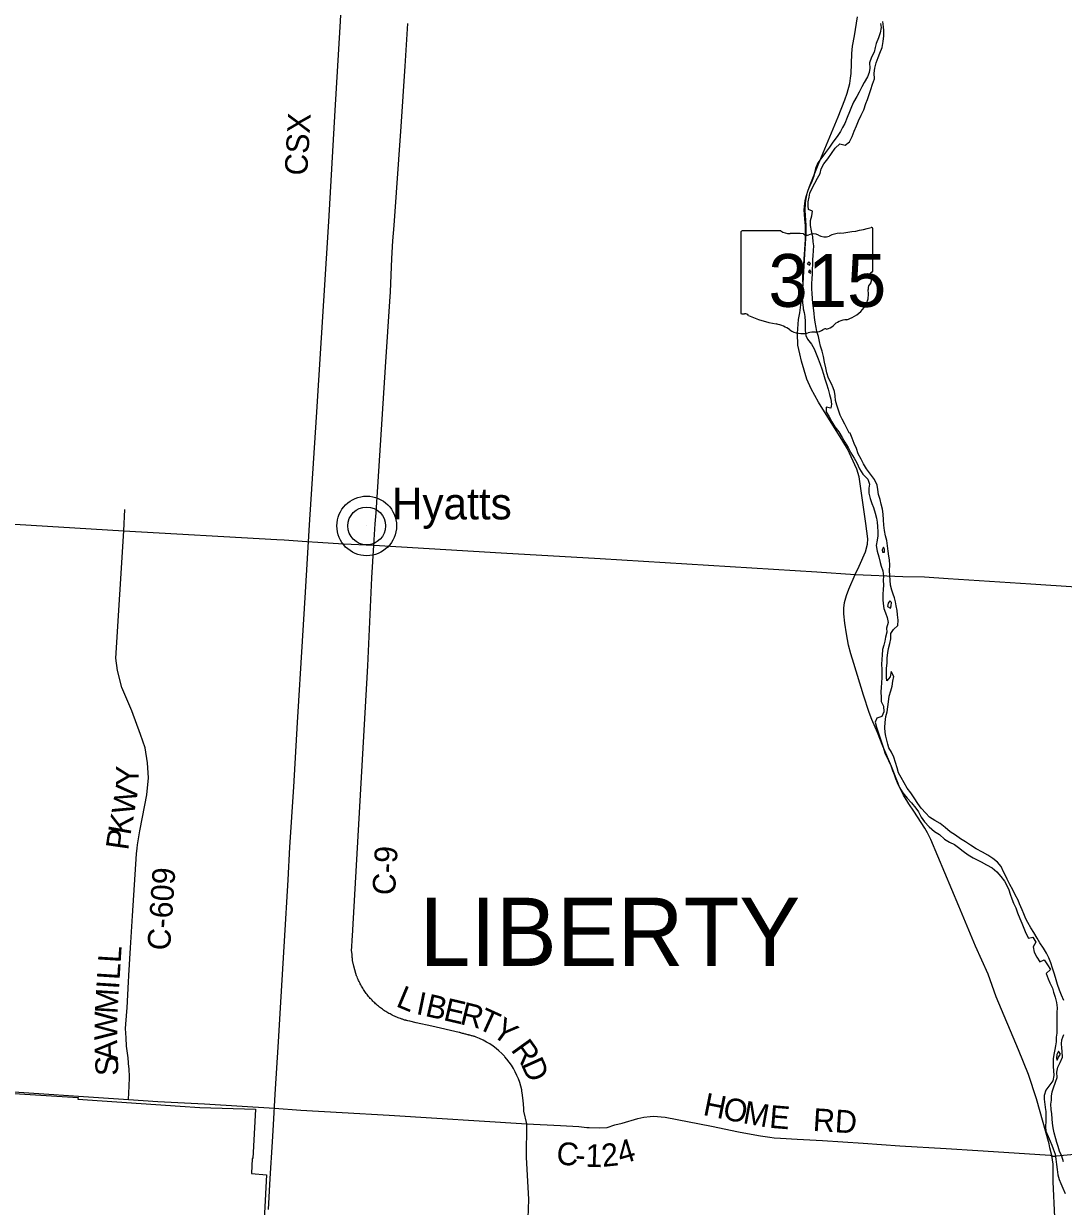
# Model space of a CAD drawing. Extents: x 1674899 to 2057726, y 653888 to 988278.
# Drawn here: x 1800519 to 1814222, y 798950 to 814535 of the extents above; entities that cross this region are included whole.
import ezdxf

# ---------------------------------------------------------------- set-up
doc = ezdxf.new("R2010")
doc.units = 0
for name, color, linetype in [('GM_X_Corporation', 7, 'Continuous'), ('GM_X_County_Road', 7, 'Continuous'), ('GM_X_County_Road_Text', 7, 'Continuous'), ('GM_X_Major_River', 7, 'Continuous'), ('GM_X_Rail_Line', 7, 'Continuous'), ('GM_X_Rail_Line_Text', 7, 'Continuous'), ('GM_X_State_Location', 7, 'Continuous'), ('GM_X_State_Route', 7, 'Continuous'), ('GM_X_State_Shield', 7, 'Continuous'), ('GM_X_Township_Text', 7, 'Continuous'), ('GM_X_Unincorporated', 7, 'Continuous'), ('GM_X_Unincorporated_Location', 7, 'Continuous'), ('GM_X_Unincorporated_Text', 7, 'Continuous')]:
    doc.layers.add(name, color=color, linetype=linetype)

msp = doc.modelspace()

# ---------------------------------------------------------------- linework, layer by layer
at = {"layer": 'GM_X_Corporation'}
msp.add_lwpolyline([(1800039, 800457), (1801236, 800382), (1801235, 800362), (1802581, 800268), (1802843, 800252), (1803573, 800232), (1803539, 799580), (1803531, 799580), (1803521, 799381), (1803720, 799367), (1803650, 798018)], dxfattribs=at)
at = {"layer": 'GM_X_County_Road'}
for points in [[(1804844, 802293), (1804843, 802302), (1804842, 802313), (1804841, 802319), (1804844, 802370), (1804849, 802458), (1804852, 802514), (1805055, 806072), (1805110, 807232), (1805136, 807661), (1805154, 807942), (1805164, 808090), (1805292, 810078), (1805346, 810873), (1805352, 810999), (1805373, 811438), (1805385, 811671), (1805404, 811873), (1805495, 813180), (1805546, 813974), (1805583, 814537)], [(1797153, 808138), (1797813, 808094), (1798478, 808064), (1798746, 808039), (1801838, 807850), (1803855, 807737), (1803954, 807731), (1804251, 807713), (1804397, 807702), (1804736, 807682), (1805136, 807661), (1806811, 807563), (1808119, 807486), (1809547, 807399), (1810973, 807310), (1811477, 807276), (1812106, 807251), (1812390, 807244), (1812704, 807223), (1813792, 807154), (1815652, 807028), (1817412, 806933), (1818544, 806864), (1818913, 806840)], [(1801838, 807850), (1801854, 808132)], [(1802014, 803669), (1802020, 803715), (1802050, 803896), (1802085, 804077), (1802143, 804374), (1802164, 804595), (1802153, 804796), (1802119, 804993), (1802057, 805167), (1801945, 805481), (1801815, 805789), (1801757, 806010), (1801735, 806174), (1801838, 807850)], [(1801953, 802776), (1801962, 802915), (1802006, 803596), (1802014, 803669)], [(1801927, 802355), (1801953, 802776)], [(1801904, 801987), (1801904, 801993), (1801927, 802355)], [(1806860, 800922), (1806855, 800928), (1806820, 800964), (1806783, 800999), (1806745, 801031), (1806705, 801061), (1806663, 801090), (1806620, 801115), (1806575, 801139), (1806529, 801160), (1806483, 801179), (1806464, 801186), (1806456, 801189), (1806449, 801191), (1806443, 801192), (1806431, 801196), (1806423, 801198), (1806414, 801200), (1806401, 801204), (1806388, 801207), (1806381, 801209), (1806371, 801212), (1806359, 801215), (1806347, 801218), (1806336, 801220), (1806324, 801223), (1806314, 801226), (1806302, 801229), (1806289, 801233), (1806283, 801235), (1806276, 801237), (1806266, 801239), (1806257, 801241), (1805899, 801322), (1805693, 801369), (1805607, 801388), (1805581, 801394), (1805570, 801397), (1805562, 801399), (1805554, 801401), (1805547, 801403), (1805539, 801405), (1805530, 801408), (1805521, 801412), (1805511, 801415), (1805503, 801418), (1805495, 801421), (1805486, 801424), (1805470, 801430), (1805454, 801436), (1805439, 801442), (1805424, 801449), (1805408, 801455), (1805393, 801462), (1805386, 801466), (1805378, 801470), (1805363, 801477), (1805349, 801485), (1805334, 801493), (1805319, 801501), (1805305, 801510), (1805291, 801518), (1805277, 801527), (1805263, 801537), (1805249, 801546), (1805236, 801556), (1805223, 801566), (1805209, 801576), (1805196, 801586), (1805184, 801597), (1805171, 801608), (1805158, 801619), (1805146, 801630), (1805134, 801642), (1805122, 801654), (1805111, 801666), (1805099, 801678), (1805088, 801690), (1805077, 801703), (1805066, 801715), (1805056, 801728), (1805045, 801741), (1805035, 801755), (1805025, 801768), (1805016, 801782), (1805006, 801795), (1804997, 801809), (1804988, 801823), (1804980, 801838), (1804971, 801852), (1804963, 801867), (1804955, 801881), (1804948, 801896), (1804940, 801911), (1804933, 801926), (1804926, 801941), (1804920, 801957), (1804914, 801972), (1804911, 801979), (1804907, 801988), (1804896, 802019), (1804882, 802065), (1804869, 802115), (1804855, 802189), (1804854, 802197), (1804852, 802214), (1804850, 802230), (1804849, 802247), (1804848, 802263), (1804847, 802274), (1804844, 802293), (1804844, 802293)], [(1801882, 801567), (1801899, 801907), (1801904, 801987)], [(1801907, 800780), (1801897, 800907), (1801875, 801062), (1801868, 801169), (1801863, 801294), (1801880, 801518), (1801882, 801567)], [(1801901, 800359), (1801911, 800535), (1801912, 800648), (1801908, 800771), (1801907, 800780)], [(1807152, 800038), (1807113, 800206), (1807110, 800245), (1807102, 800345), (1807090, 800444), (1807086, 800469), (1807083, 800485), (1807071, 800534), (1807057, 800582), (1807040, 800629), (1807020, 800676), (1806999, 800721), (1806974, 800766), (1806948, 800808), (1806919, 800850), (1806888, 800890), (1806860, 800922)], [(1796520, 800687), (1796632, 800682), (1798065, 800600), (1798576, 800566), (1800057, 800481), (1801901, 800359), (1802286, 800331), (1802901, 800301), (1803824, 800245), (1804171, 800217), (1804715, 800188)], [(1804715, 800188), (1804715, 800188), (1805337, 800150)], [(1805337, 800150), (1807152, 800038)], [(1807071, 796914), (1807086, 797176), (1807115, 797807), (1807169, 798793), (1807176, 799039), (1807148, 799599), (1807152, 800038)], [(1807152, 800038), (1807595, 800015), (1807835, 800002), (1807942, 799990), (1807972, 799989)], [(1807972, 799989), (1808102, 799984), (1808211, 799987), (1808312, 800022), (1808409, 800047), (1808615, 800108), (1808695, 800123), (1808776, 800134), (1808826, 800138), (1808921, 800131), (1808973, 800123), (1809585, 800007), (1809940, 799932), (1810107, 799900), (1810229, 799878), (1810291, 799868), (1810353, 799860), (1810412, 799854), (1810492, 799848), (1810714, 799837), (1811046, 799817), (1811584, 799784), (1812065, 799747), (1812676, 799710), (1813093, 799684), (1813708, 799647), (1814050, 799626), (1814069, 799619)], [(1814069, 799619), (1814069, 799619), (1814083, 799612), (1814092, 799610), (1814102, 799610), (1814111, 799611), (1814133, 799614), (1814460, 799647), (1814566, 799659)]]:
    msp.add_lwpolyline(points, dxfattribs=at)
at = {"layer": 'GM_X_Major_River'}
for points in [[(1811812, 814536), (1811819, 814486), (1811809, 814412), (1811785, 814346), (1811754, 814274), (1811740, 814222), (1811730, 814158), (1811693, 814092), (1811667, 814020), (1811672, 813948), (1811664, 813892), (1811642, 813832), (1811597, 813760), (1811567, 813704), (1811530, 813634)], [(1811640, 813535), (1811685, 813667), (1811705, 813737), (1811731, 813809), (1811730, 813881), (1811738, 813949), (1811755, 814017), (1811783, 814091), (1811805, 814145), (1811832, 814219), (1811846, 814299), (1811855, 814375), (1811857, 814443), (1811853, 814495), (1811844, 814564)], [(1811530, 813634), (1811500, 813576), (1811458, 813502), (1811431, 813438), (1811403, 813375), (1811372, 813299), (1811344, 813219), (1811312, 813167), (1811287, 813113), (1811241, 813047), (1811185, 812971), (1811138, 812906), (1811088, 812836), (1811040, 812772), (1810985, 812702), (1810955, 812624), (1810944, 812574), (1810932, 812524), (1810906, 812456), (1810875, 812388), (1810853, 812336), (1810833, 812265), (1810814, 812199), (1810806, 812126), (1810803, 812076), (1810807, 812026), (1810811, 811960), (1810818, 811876), (1810820, 811816), (1810819, 811690), (1810817, 811624), (1810810, 811558), (1810806, 811497), (1810801, 811431), (1810799, 811367), (1810791, 811301), (1810786, 811225), (1810782, 811153), (1810787, 811101), (1810785, 811043), (1810781, 810973), (1810780, 810923), (1810782, 810855), (1810792, 810796)], [(1811397, 809144), (1811367, 809206), (1811340, 809259), (1811308, 809325), (1811280, 809377), (1811263, 809427), (1811235, 809506), (1811220, 809570), (1811214, 809630), (1811204, 809688), (1811187, 809738), (1811165, 809790), (1811128, 809865), (1811106, 809933), (1811092, 809999), (1811075, 810072), (1811063, 810150), (1811042, 810218), (1811022, 810286), (1811007, 810348), (1810995, 810413), (1810973, 810477), (1810962, 810531), (1810950, 810603), (1810943, 810663), (1810937, 810715), (1810929, 810788), (1810920, 810850), (1810916, 810910), (1810911, 810982), (1810909, 811034), (1810905, 811110), (1810912, 811174), (1810914, 811238), (1810917, 811304), (1810919, 811356), (1810921, 811425), (1810924, 811475), (1810930, 811545), (1810932, 811607), (1810923, 811659), (1810919, 811727), (1810904, 811803), (1810888, 811874), (1810889, 811942), (1810907, 812002), (1810915, 812066), (1810861, 812086), (1810858, 812136), (1810860, 812188), (1810872, 812250), (1810881, 812302), (1810913, 812368), (1810947, 812434), (1810980, 812498), (1811016, 812562), (1811031, 812620), (1811067, 812686), (1811119, 812755), (1811166, 812825), (1811216, 812895), (1811276, 812953), (1811348, 812932), (1811405, 812978), (1811437, 813046), (1811467, 813116), (1811494, 813190), (1811522, 813254), (1811557, 813329), (1811591, 813401), (1811619, 813483), (1811640, 813535)], [(1810869, 811395), (1810845, 811371), (1810875, 811353)], [(1810875, 811353), (1810891, 811375), (1810869, 811395)], [(1810879, 811289), (1810864, 811271), (1810888, 811247)], [(1810888, 811247), (1810892, 811261), (1810879, 811289)], [(1810792, 810796), (1810793, 810778), (1810807, 810728), (1810817, 810678), (1810820, 810610), (1810820, 810560), (1810818, 810492), (1810827, 810426), (1810851, 810375), (1810902, 810311), (1810940, 810251), (1810962, 810182), (1810989, 810116), (1811019, 810046), (1811038, 809986), (1811060, 809915), (1811078, 809853), (1811101, 809787), (1811121, 809719), (1811138, 809650), (1811156, 809586), (1811165, 809520), (1811159, 809466), (1811097, 809480), (1811097, 809420), (1811136, 809354), (1811172, 809288), (1811210, 809223), (1811261, 809157), (1811305, 809083), (1811344, 809018), (1811388, 808950), (1811423, 808880), (1811463, 808809), (1811498, 808749), (1811534, 808668), (1811581, 808600), (1811647, 808534), (1811665, 808465), (1811660, 808415), (1811660, 808347), (1811677, 808279), (1811699, 808213), (1811719, 808159), (1811740, 808084), (1811758, 808020), (1811767, 807966), (1811773, 807908), (1811777, 807838), (1811776, 807786), (1811768, 807730), (1811757, 807658), (1811767, 807584), (1811788, 807507), (1811806, 807435), (1811822, 807385), (1811841, 807325), (1811851, 807253), (1811847, 807200), (1811850, 807136), (1811846, 807080), (1811841, 807018), (1811845, 806942), (1811849, 806892), (1811858, 806826), (1811878, 806772), (1811901, 806708), (1811911, 806645), (1811893, 806571), (1811894, 806517), (1811880, 806449), (1811868, 806399), (1811855, 806345), (1811839, 806289), (1811832, 806215), (1811828, 806159), (1811826, 806091), (1811829, 806027), (1811829, 805921), (1811826, 805845), (1811820, 805793), (1811815, 805727), (1811821, 805661), (1811823, 805603), (1811850, 805540), (1811858, 805468), (1811831, 805406), (1811765, 805385), (1811741, 805329), (1811759, 805265), (1811780, 805197), (1811800, 805146), (1811847, 805002), (1811868, 804928), (1811892, 804878), (1811918, 804823), (1811947, 804759), (1811971, 804691), (1811992, 804641), (1812008, 804588), (1812032, 804534)], [(1813461, 803310), (1813433, 803360), (1813402, 803427), (1813354, 803487), (1813292, 803533), (1813225, 803576), (1813157, 803616), (1813075, 803659), (1813000, 803709), (1812932, 803752), (1812868, 803794), (1812799, 803839), (1812731, 803885), (1812666, 803944), (1812600, 803996), (1812528, 804033), (1812459, 804079), (1812409, 804130), (1812347, 804198), (1812302, 804260), (1812254, 804331), (1812213, 804397), (1812163, 804461), (1812124, 804530), (1812086, 804600), (1812051, 804664), (1812031, 804730), (1812011, 804799), (1811990, 804869), (1811958, 804935), (1811923, 804991), (1811907, 805042), (1811895, 805094), (1811882, 805144), (1811872, 805194), (1811870, 805258), (1811873, 805326), (1811883, 805406), (1811900, 805466), (1811908, 805534), (1811917, 805598), (1811925, 805674), (1811947, 805742), (1811964, 805806), (1811974, 805870), (1811989, 805934), (1811953, 805998), (1811939, 805926), (1811894, 805873), (1811891, 805925), (1811891, 805991), (1811893, 806041), (1811898, 806107), (1811902, 806177), (1811907, 806245), (1811919, 806299), (1811937, 806365), (1811948, 806427), (1811950, 806497), (1811982, 806553), (1812039, 806605), (1812045, 806673), (1812038, 806745), (1812032, 806801), (1812020, 806865), (1812011, 806915), (1811997, 806967), (1811981, 807019), (1811962, 807070), (1811946, 807136), (1811940, 807202), (1811937, 807262), (1811931, 807328), (1811936, 807398), (1811930, 807468), (1811924, 807518), (1811915, 807585), (1811903, 807653), (1811894, 807723), (1811876, 807785), (1811863, 807857), (1811857, 807925), (1811853, 807996), (1811848, 808072), (1811838, 808138), (1811821, 808204), (1811807, 808264), (1811786, 808330), (1811778, 808395), (1811766, 808455), (1811733, 808527), (1811679, 808597), (1811628, 808670), (1811588, 808736), (1811557, 808797), (1811519, 808865), (1811494, 808937), (1811466, 809001), (1811438, 809074), (1811411, 809140), (1811397, 809144)], [(1811851, 807637), (1811833, 807603), (1811839, 807569), (1811865, 807569)], [(1811865, 807569), (1811867, 807595), (1811865, 807609), (1811851, 807637)], [(1811935, 806928), (1811911, 806900), (1811904, 806856), (1811942, 806833)], [(1811942, 806833), (1811954, 806865), (1811959, 806905), (1811935, 806928)], [(1812032, 804534), (1812061, 804468), (1812105, 804398), (1812162, 804327), (1812220, 804265), (1812277, 804198), (1812311, 804148), (1812347, 804080), (1812390, 804018), (1812454, 803949), (1812523, 803889), (1812591, 803848), (1812657, 803790), (1812720, 803749), (1812786, 803719), (1812840, 803678), (1812903, 803628), (1812967, 803580), (1813033, 803541), (1813085, 803515), (1813140, 803488), (1813210, 803452), (1813282, 803409), (1813347, 803357), (1813399, 803295), (1813448, 803234), (1813480, 803170), (1813502, 803120), (1813521, 803062), (1813545, 803001), (1813567, 802947), (1813594, 802883), (1813618, 802817), (1813647, 802743), (1813673, 802682), (1813702, 802616), (1813728, 802550), (1813761, 802482), (1813818, 802499), (1813859, 802431), (1813823, 802369), (1813836, 802301), (1813872, 802235), (1813913, 802174), (1813968, 802200), (1814011, 802134), (1814051, 802069), (1813996, 802020), (1814020, 801950), (1814046, 801895), (1814077, 801823), (1814091, 801773), (1814114, 801705), (1814130, 801637), (1814139, 801566), (1814135, 801504), (1814137, 801424), (1814138, 801352), (1814136, 801302), (1814135, 801230), (1814129, 801180), (1814127, 801116), (1814118, 801066), (1814110, 801016), (1814098, 800950), (1814087, 800892), (1814087, 800842), (1814089, 800788), (1814092, 800738), (1814096, 800672), (1814083, 800604), (1814031, 800532), (1813991, 800479), (1813970, 800411), (1813970, 800361), (1813979, 800292), (1813987, 800222)], [(1814228, 801662), (1814196, 801732), (1814171, 801798), (1814143, 801871), (1814126, 801935), (1814104, 802011), (1814079, 802089), (1814055, 802159), (1814032, 802224), (1814000, 802288), (1813961, 802354), (1813913, 802421), (1813877, 802485), (1813834, 802557), (1813794, 802620), (1813755, 802688), (1813727, 802738), (1813702, 802804), (1813678, 802856), (1813646, 802935), (1813625, 802985), (1813589, 803053), (1813556, 803121), (1813518, 803192), (1813483, 803260), (1813461, 803310)], [(1814223, 799538), (1814201, 799609), (1814173, 799677), (1814154, 799737), (1814138, 799789), (1814123, 799839), (1814101, 799919), (1814087, 799984), (1814080, 800048), (1814074, 800102), (1814071, 800168), (1814063, 800224), (1814059, 800298), (1814064, 800350), (1814068, 800400), (1814076, 800458), (1814093, 800512), (1814117, 800584), (1814140, 800646), (1814136, 800716), (1814150, 800782), (1814179, 800844), (1814211, 800916), (1814208, 800990), (1814200, 801040), (1814198, 801090), (1814201, 801144), (1814227, 801216)], [(1814160, 800996), (1814136, 800952), (1814131, 800902), (1814139, 800874)], [(1814139, 800874), (1814157, 800914), (1814185, 800956), (1814160, 800996)], [(1813987, 800222), (1813991, 800206), (1813990, 800074), (1813988, 800002), (1813993, 799940), (1814023, 799872), (1814050, 799810), (1814070, 799758), (1814088, 799707), (1814113, 799639), (1814125, 799573), (1814132, 799501), (1814140, 799435), (1814151, 799367), (1814167, 799303), (1814187, 799252), (1814214, 799188), (1814244, 799118)]]:
    msp.add_lwpolyline(points, dxfattribs=at)
at = {"layer": 'GM_X_Rail_Line'}
msp.add_lwpolyline([(1803745, 798910), (1803770, 799318), (1803800, 799802), (1803812, 800022), (1803836, 800426), (1803878, 801117), (1803909, 801640), (1803957, 802442), (1804005, 803254), (1804029, 803681), (1804080, 804478), (1804130, 805325), (1804195, 806396), (1804233, 807042), (1804286, 807930), (1804378, 809351), (1804539, 811926), (1804626, 813390), (1804692, 814494), (1804844, 817257)], dxfattribs=at)
at = {"layer": 'GM_X_State_Route'}
for points in [[(1814046, 799719), (1814033, 799773), (1813866, 800366), (1813763, 800686), (1813633, 801011), (1813335, 801709), (1813229, 802008), (1813066, 802380), (1812846, 802906), (1812474, 803784), (1812432, 803871), (1812398, 803934), (1812252, 804156), (1812185, 804255), (1812173, 804274), (1812117, 804367), (1812069, 804464), (1811955, 804745), (1811845, 805016), (1811772, 805192), (1811699, 805366), (1811663, 805457), (1811586, 805686), (1811462, 806103), (1811422, 806230), (1811390, 806346), (1811366, 806494), (1811344, 806636), (1811331, 806756), (1811328, 806834), (1811339, 806907), (1811363, 807000), (1811396, 807084), (1811477, 807276), (1811532, 807384), (1811613, 807576), (1811639, 807676), (1811643, 807748), (1811620, 807949), (1811532, 808561), (1811500, 808662), (1811375, 808930), (1811317, 809033), (1810997, 809547), (1810899, 809721), (1810839, 809851), (1810772, 810087), (1810748, 810186), (1810723, 810300), (1810719, 810451), (1810730, 810638), (1810750, 810726), (1810788, 811039), (1810819, 811571), (1810831, 811764), (1810832, 811874), (1810825, 812009), (1810821, 812072), (1810825, 812175), (1810836, 812251), (1810851, 812314), (1810876, 812387), (1810989, 812675), (1811252, 813309), (1811341, 813530), (1811373, 813618), (1811406, 813748), (1811418, 813816), (1811425, 813877), (1811430, 814007), (1811436, 814142), (1811445, 814240), (1811468, 814373), (1811509, 814626)], [(1814274, 796960), (1814214, 797077), (1814186, 797179), (1814154, 797878), (1814090, 799272), (1814087, 799504), (1814069, 799619), (1814046, 799719)]]:
    msp.add_lwpolyline(points, dxfattribs=at)
at = {"layer": 'GM_X_State_Shield'}
for p, q in [((1809970, 811785), (1809970, 810729)), ((1810497, 811804), (1809987, 811804)), ((1811710, 811277), (1811710, 811830)), ((1811710, 811277), (1811710, 811277))]:
    msp.add_line(p, q, dxfattribs=at)
for centre, major_axis, start_param, end_param in [((1811090, 813244), (1845, 0), 4.814394, 5.042369), ((1811691, 811832), (19.4, 0), 6.141152, 7.989035), ((1809990, 811788), (20.2, 0), 1.712693, 3.28349), ((1810618, 811926), (196, 0), 4.042523, 4.731795), ((1810683, 811210), (702, 0), 1.404758, 1.657858), ((1810842, 811793), (56.4, 0), 3.836095, 5.185415), ((1810925, 811671), (117, 0), 0.950623, 2.079405), ((1811077, 811838), (141, 0), 4.081561, 5.145723), ((1811326, 811481), (371, 0), 1.699011, 2.107814), ((1811706, 811236), (30, 0), 1.883978, 3.671073), ((1811515, 811167), (180, 0), 5.934695, 6.695948), ((1811690, 811275), (20.7, 0), 5.05454, 6.418171), ((1811780, 811046), (131, 0), 2.387724, 3.262537), ((1811194, 810975), (462, 0), 5.101752, 6.440018), ((1809990, 810726), (20.3, 0), 3.00124, 4.508301), ((1809993, 810835), (155, 0), 4.665946, 4.897461), ((1810025, 810668), (56, 0), 0.519207, 1.627899), ((1810732, 811617), (1333, 0), 4.195997, 4.488961), ((1811388, 810432), (253, 0), 1.647645, 2.488434), ((1810334, 810254), (417, 0), 0.823519, 1.323587), ((1810785, 810663), (265, 0), 4.026481, 4.996735), ((1810938, 810297), (217, 0), 1.495662, 1.94098), ((1810957, 810583), (141, 0), 4.691044, 5.507374), ((1811085, 810481), (39.7, 0), 1.147584, 2.315152), ((1811068, 810626), (149, 0), 4.937069, 5.64225)]:
    msp.add_ellipse(centre, major_axis=major_axis, ratio=0.8, start_param=start_param, end_param=end_param, dxfattribs=at)
at = {"layer": 'GM_X_Unincorporated'}
for radius in [393, 249]:
    msp.add_circle((1805040, 807916), radius, dxfattribs=at)
at = {"layer": 'GM_X_Unincorporated_Location'}
msp.add_line((1805040, 807916), (1805040, 807916), dxfattribs=at)

# ---------------------------------------------------------------- texts
at = {"layer": 'GM_X_County_Road_Text'}
for s, rotation, p in [('Y', 89.0624, (1802034, 804486)), ('W', 80.4767, (1801972, 804095)), ('K', 79.8364, (1801925, 803832)), ('P', 81.711, (1801896, 803634)), ('C-9', 86.769, (1805413, 803044)), ('C-609', 86.1488, (1802447, 802315)), ('L', 86.3934, (1801797, 802152)), ('L', 86.3935, (1801783, 801928)), ('I', 86.3954, (1801775, 801805)), ('M', 86.5097, (1801755, 801480)), ('L', 337.2738, (1805413, 801591)), ('I', 348.4399, (1805680, 801486)), ('B', 346.945, (1805799, 801461)), ('E', 346.9461, (1806039, 801406)), ('R', 346.1143, (1806256, 801355)), ('T', 335.5571, (1806482, 801301)), ('W', 89.271, (1801751, 801136)), ('Y', 323.9734, (1806672, 801216)), ('A', 92.2226, (1801761, 800877)), ('R', 305.7169, (1806932, 801012)), ('S', 92.4477, (1801770, 800675)), ('D', 294.1631, (1807068, 800826)), ('H', 348.7205, (1809461, 800155)), ('O', 348.3073, (1809720, 800103)), ('M', 349.7534, (1809987, 800048)), ('E', 355.2552, (1810339, 799986)), ('RD', 356.5467, (1810915, 799944)), ('4', 16.657, (1808392, 799500)), ('C', 354.5667, (1807531, 799506)), ('1', 358.2285, (1807920, 799472)), ('2', 6.1726, (1808150, 799468)), ('-', 355.6785, (1807782, 799482))]:
    msp.add_text(s, height=300, rotation=rotation, dxfattribs=at).set_placement(p)
at = {"layer": 'GM_X_Rail_Line_Text'}
msp.add_text('CSX', height=299, rotation=86.5557, dxfattribs=at).set_placement((1804255, 812527))
at = {"layer": 'GM_X_State_Location'}
msp.add_text('315', height=1, rotation=0, dxfattribs=at).set_placement((1810468, 811114))
for s in ['s', 'r']:
    msp.add_text(s, height=1, dxfattribs=at).set_placement((1810821, 811187))
at = {"layer": 'GM_X_State_Shield'}
msp.add_text('315', height=696.1, dxfattribs=at).set_placement((1810335, 810803))
at = {"layer": 'GM_X_Township_Text'}
msp.add_text('LIBERTY', height=900, rotation=0, dxfattribs=at).set_placement((1805738, 802117))
at = {"layer": 'GM_X_Unincorporated_Text'}
msp.add_text('Hyatts', height=417, rotation=0, dxfattribs=at).set_placement((1805372, 808002))

doc.saveas('drawing.dxf')
